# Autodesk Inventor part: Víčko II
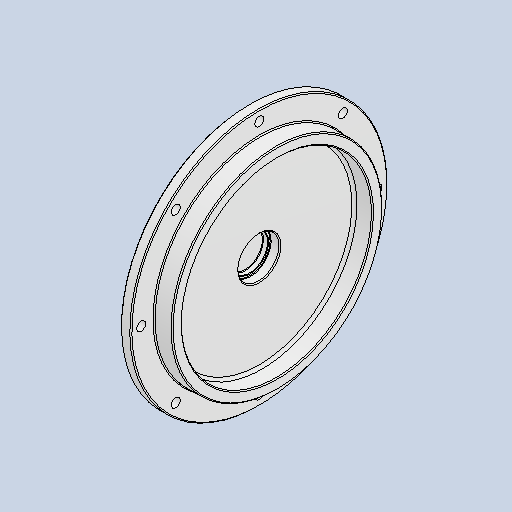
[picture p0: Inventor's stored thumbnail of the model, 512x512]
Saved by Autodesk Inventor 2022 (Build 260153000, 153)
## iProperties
Created: 2025-05
Part Number: Víčko II
Material: Všeobecné
Document SubType Name: Modeling
Designer: jbart
Density: 1 g/cm^3
Appearance: Hladká – bílá
Mass: 5770.13 g
Surface Area: 5421.67 cm^2
Volume: 5770.13 cm^3
Author: jbart
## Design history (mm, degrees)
sketch "Náčrt1"
  geometry: L1 (0, 0)-(47.958, 0); L2 (0, 0)-(0, 35); L3 (0, 35)-(10, 35); L4 (10, 35)-(10, 40); L5 (10, 40)-(28, 40); L6 (28, 40)-(28, 185); L7 (28, 185)-(63, 185); L8 (63, 185)-(63, 205); L9 (63, 205)-(28, 205); L10 (28, 205)-(28, 250); L11 (28, 250)-(8, 250); L12 (8, 250)-(8, 130); L13 (8, 130)-(-20, 130); L14 (-20, 130)-(-20, 100); L15 (-20, 100)-(-10, 100); L16 (-10, 100)-(-10, 0); L17 (-10, 0)-(0, 0)
  constraints: 34 end point, 11 perpendicular, 3 point on line, 3 vertical, 2 horizontal
  dimensions: "d1" = 80 diameter of L5 L1; "d2" = 18 distance of L4.end L5.end; "d3" = 10 distance of L2.end L3.end; "d4" = 70 diameter of L3 L1; "d5" = 370 diameter of L7 L1; "d6" = 35 distance between parallel lines of L8 L10; "d7" = 500 diameter of L11 L1; "d8" = 410 diameter of L9 L1; "d9" = 20 distance of L10.end L11.end; "d10" = 10 distance between parallel lines of L16 L14; "d11" = 200 diameter of L15 L1; "d12" = 260 diameter of L13 L1; "d13" = 10 distance between parallel lines of L2 L16
revolve "Rotace1" sketch "Náčrt1" stored, may be unused: angle "d14" = 90 deg
sketch "Náčrt2" dims "d15" = 460
  geometry: L1 (0, 0)-(0, 230); 2 further points
  constraints: 2 coincident, 2 end point, 1 vertical, 1 vertical alignment, 2 other
hole "Díra1" sketch "Náčrt2" at (0, 230) diameter "d16" = 17.5; stored, may be unused: countersink angle "d20" = 90 deg, drill point angle "d22" = 118 deg; dims "d17" = 6, "d18" = 20, "d19" = 12, "d21" = 8
pattern_circular "Kruhové pole1" dims angle "d24" = 360 deg
chamfer "Zkosení1" distance "d26" = 2; stored, may be unused: second distance "d27" = 2, angle "d28" = 45 deg
fillet "Zaoblení1" dims "d29" = 2
fillet "Zaoblení2" dims "d30" = 1
sketch "Náčrt3" dims "d31" = 230
  geometry: L1 (0, 0)-(0, 115); 2 further points
  constraints: 2 coincident, 2 end point, 1 vertical, 1 vertical alignment, 2 other
hole "Díra2" sketch "Náčrt3" at (0, 115) diameter "d32" = 10.106; stored, may be unused: countersink angle "d36" = 90 deg, drill point angle "d38" = 118 deg; dims "d33" = 15, "d34" = 4, "d35" = 2, "d37" = 20
pattern_circular "Kruhové pole2" dims angle "d40" = 360 deg
fillet "Zaoblení3" dims "d42" = 1
chamfer "Zkosení2" distance "d43" = 1; stored, may be unused: second distance "d44" = 2, angle "d45" = 45 deg
fillet "Zaoblení4" dims "d46" = 5
node "Těleso1"
